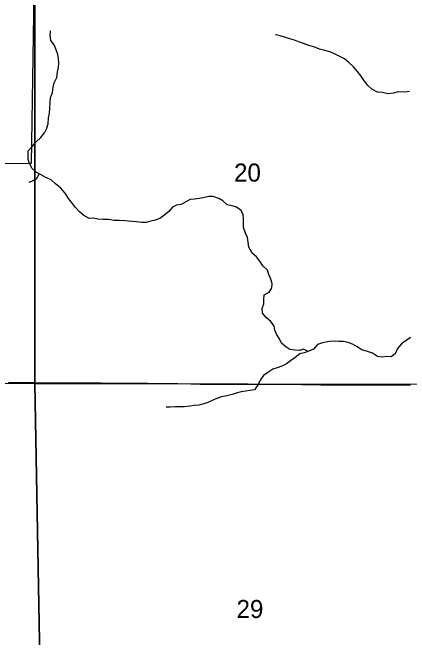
# Model space of a CAD drawing. Extents: x 0 to 34, y 0 to 22.
# Drawn here: x 4.028 to 4.949, y 18.295 to 19.744 of the extents above; entities that cross this region are included whole.
import ezdxf

# ---------------------------------------------------------------- set-up
doc = ezdxf.new("R2010")
doc.units = 0
for name, color, linetype in [('GM_X_Corporation', 7, 'Continuous'), ('GM_X_Minor_River', 7, 'Continuous'), ('GM_X_Section', 7, 'Continuous'), ('GM_X_Section_Text', 7, 'Continuous'), ('GM_X_Township_Road', 7, 'Continuous')]:
    doc.layers.add(name, color=color, linetype=linetype)

msp = doc.modelspace()

# ---------------------------------------------------------------- linework, layer by layer
at = {"layer": 'GM_X_Corporation'}
msp.add_lwpolyline([(4.0712, 19.394), (3.5643, 19.3915), (3.0631, 19.3888), (3.0588, 19.9042), (3.0542, 20.415), (3.5567, 20.4072), (4.0701, 20.4238), (4.0786, 19.8867)], close=True, dxfattribs=at)
at = {"layer": 'GM_X_Minor_River'}
for points in [[(4.1322, 19.6065), (4.1346, 19.6167), (4.1354, 19.6266), (4.1344, 19.6376), (4.1329, 19.6471), (4.1292, 19.6573), (4.1248, 19.6691), (4.1169, 19.6795), (4.1155, 19.6905), (4.1156, 19.7), (4.1152, 19.7015)], [(4.949, 19.5614), (4.9372, 19.5592), (4.9232, 19.5601), (4.9115, 19.5568), (4.8982, 19.5558), (4.8861, 19.5586), (4.8744, 19.5594), (4.8616, 19.5664), (4.851, 19.576), (4.8428, 19.5871), (4.8364, 19.5966), (4.8282, 19.6077), (4.8185, 19.618), (4.8079, 19.628), (4.7978, 19.6368), (4.7744, 19.6484), (4.7642, 19.6527), (4.7521, 19.6558), (4.7397, 19.6594), (4.7265, 19.6648), (4.7155, 19.668), (4.703, 19.6726), (4.6932, 19.6754), (4.6819, 19.6797), (4.6709, 19.6828), (4.6607, 19.6859), (4.649, 19.6899), (4.6392, 19.6926), (4.6377, 19.6926)], [(4.7137, 18.9584), (4.7031, 18.964), (4.6936, 18.961), (4.6833, 18.9615), (4.6712, 18.9631), (4.6615, 18.9693), (4.6517, 18.9774), (4.6468, 18.9876), (4.6405, 18.9983), (4.6364, 19.0079), (4.6346, 19.0174), (4.6267, 19.0277), (4.6166, 19.0361), (4.6076, 19.0472), (4.6069, 19.0582), (4.6108, 19.0688), (4.6105, 19.079), (4.6114, 19.09), (4.6228, 19.096), (4.6293, 19.1058), (4.6301, 19.116), (4.6268, 19.1263), (4.6227, 19.137), (4.6194, 19.1469), (4.6081, 19.1572), (4.6018, 19.1675), (4.5939, 19.1778), (4.5838, 19.1863), (4.5763, 19.2004), (4.5745, 19.2118), (4.5727, 19.2228), (4.5683, 19.2327), (4.5638, 19.2457), (4.5635, 19.2559), (4.5636, 19.2658), (4.5626, 19.2753), (4.5585, 19.2852), (4.5472, 19.2933), (4.5374, 19.296), (4.526, 19.2984), (4.5159, 19.3076), (4.5061, 19.313), (4.4933, 19.3173), (4.483, 19.3178), (4.4728, 19.3152), (4.461, 19.3134), (4.45, 19.3117), (4.4402, 19.311), (4.4299, 19.305), (4.4193, 19.2994), (4.4086, 19.2973), (4.3988, 19.2928), (4.3907, 19.2826), (4.3812, 19.2755), (4.3694, 19.2665), (4.3591, 19.2628), (4.3489, 19.2603), (4.3382, 19.2573), (4.328, 19.2574), (4.3155, 19.2591), (4.3057, 19.2599), (4.2883, 19.2616), (4.2758, 19.2618), (4.2637, 19.2622), (4.2508, 19.2643), (4.238, 19.264), (4.2258, 19.2649), (4.2156, 19.2673), (4.2054, 19.2666), (4.1934, 19.2736), (4.1832, 19.282), (4.1738, 19.292), (4.1667, 19.3015), (4.1581, 19.3134), (4.1499, 19.3256), (4.139, 19.3378), (4.1273, 19.3474), (4.1172, 19.3562), (4.1051, 19.3617), (4.0942, 19.3675), (4.0829, 19.3744), (4.0731, 19.3828), (4.0675, 19.3939), (4.0642, 19.4038), (4.0644, 19.4235), (4.0743, 19.4344), (4.0831, 19.4442), (4.0934, 19.4547), (4.1022, 19.4649), (4.1072, 19.4758), (4.1107, 19.486), (4.1112, 19.5001), (4.114, 19.5111), (4.1144, 19.522), (4.1149, 19.5357), (4.1162, 19.5467), (4.1208, 19.5588), (4.1224, 19.5709), (4.1248, 19.5815), (4.131, 19.5932), (4.1322, 19.6065)], [(4.0897, 19.3702), (4.0824, 19.3577), (4.0721, 19.3525), (4.0656, 19.3503)], [(4.9506, 18.9908), (4.941, 18.984), (4.93, 18.9762), (4.9208, 18.9652), (4.9154, 18.9528), (4.9059, 18.9457), (4.896, 18.9469), (4.8862, 18.9451), (4.8748, 18.9467), (4.8632, 18.9544), (4.8511, 18.9587), (4.8382, 18.9626), (4.8273, 18.9692), (4.8164, 18.9754), (4.8066, 18.9789), (4.7952, 18.9813), (4.785, 18.9814), (4.7725, 18.9826), (4.763, 18.9816), (4.7471, 18.9787), (4.7353, 18.9746), (4.7262, 18.9637), (4.7151, 18.9589), (4.7045, 18.9552), (4.6943, 18.9527), (4.6824, 18.944), (4.6725, 18.9369), (4.663, 18.9298), (4.6527, 18.9246), (4.6421, 18.9202), (4.6315, 18.9172), (4.6204, 18.9097), (4.6101, 18.903), (4.6021, 18.8917), (4.5978, 18.8819), (4.589, 18.8698), (4.5784, 18.8677), (4.5682, 18.8662), (4.5579, 18.8648), (4.5469, 18.8615), (4.5371, 18.859), (4.5253, 18.856), (4.5124, 18.8531), (4.5014, 18.8494), (4.4907, 18.845), (4.4809, 18.8398), (4.4714, 18.8372), (4.4604, 18.8343), (4.4494, 18.8329), (4.4391, 18.8318), (4.427, 18.8304), (4.416, 18.8298), (4.4054, 18.8299), (4.3937, 18.8296), (4.3846, 18.8297)]]:
    msp.add_lwpolyline(points, dxfattribs=at)
at = {"layer": 'GM_X_Section'}
for points in [[(4.0799, 19.8852), (4.08, 18.8834), (3.073, 18.8909), (3.0592, 19.8987), (3.0869, 19.8862)], [(5.0715, 19.8844), (5.0689, 18.882), (4.08, 18.8834), (4.0799, 19.8852)], [(4.0919, 18.2003), (4.08, 18.8834), (3.073, 18.8909), (3.0924, 17.8824), (4.0336, 17.8765), (4.0336, 18.2003)], [(5.0723, 18.2003), (5.0689, 18.882), (4.08, 18.8834), (4.0919, 18.2003)]]:
    msp.add_lwpolyline(points, close=True, dxfattribs=at)
at = {"layer": 'GM_X_Township_Road'}
msp.add_lwpolyline([(4.0189, 18.8871), (4.0531, 18.8866), (4.081, 18.8865), (4.2084, 18.8855), (4.2332, 18.8854), (4.2736, 18.8851), (4.342, 18.8848), (4.3762, 18.8843), (4.4104, 18.8839), (4.4414, 18.8832), (4.4632, 18.8829), (4.5004, 18.8828), (4.5471, 18.8825), (4.6993, 18.8818), (4.7148, 18.8818), (4.7428, 18.8815), (4.7988, 18.8811), (4.8423, 18.8812), (4.8734, 18.8813), (4.9511, 18.8812)], dxfattribs=at)

# ---------------------------------------------------------------- texts
at = {"layer": 'GM_X_Section_Text'}
for s, p in [('20', (4.5417, 19.3522)), ('29', (4.5475, 18.3406))]:
    msp.add_text(s, height=0.04186, rotation=0, dxfattribs=at).set_placement(p)

doc.saveas('drawing.dxf')
